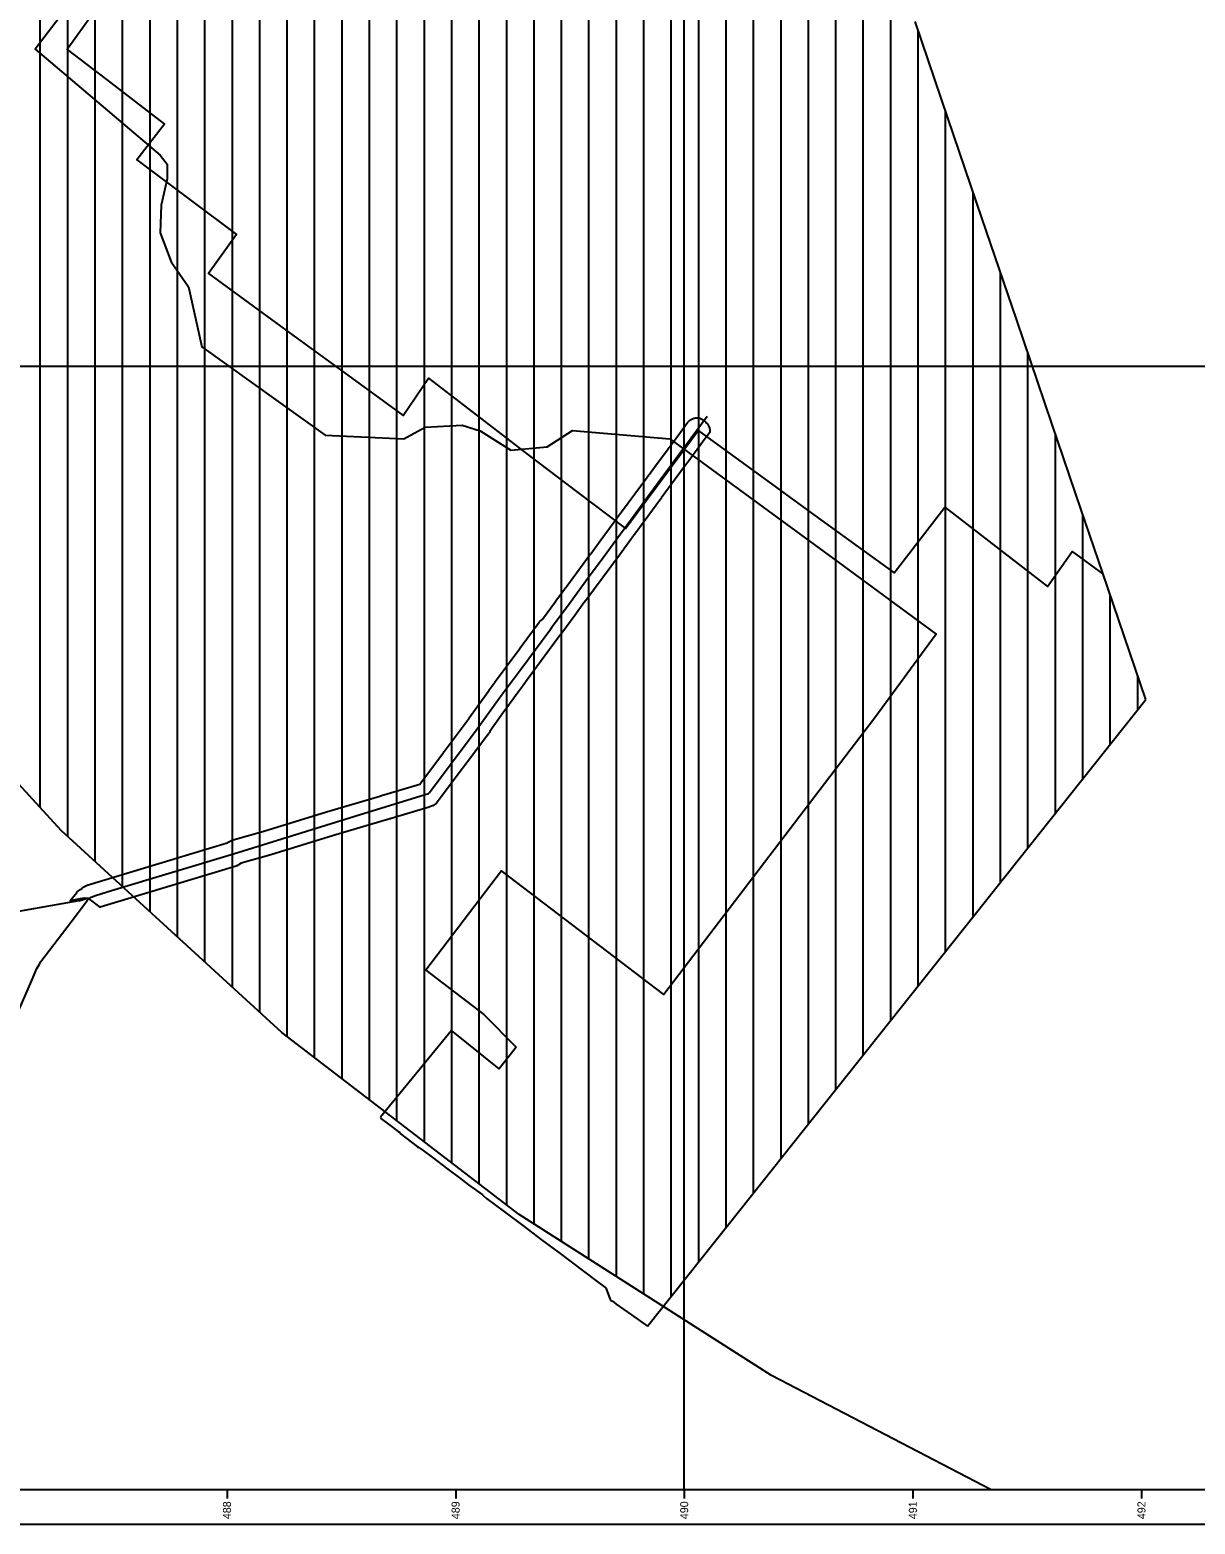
# Model space of a CAD drawing. Extents: x 468834 to 503362, y 294936 to 320859.
# Drawn here: x 487137 to 492234, y 294936 to 301471 of the extents above; entities that cross this region are included whole.
import ezdxf

# ---------------------------------------------------------------- set-up
doc = ezdxf.new("R2010")
doc.units = 0
for name, color, linetype in [('7311020103_no 10 līdz 25 kilometriem garas dabiskas ūdensteces vides un dabas resursu aizsardzības aizsargjoslas teritorija lauku apvidos', 7, 'Continuous'), ('7311080102_vides un dabas resursu aizsardzības aizsargjoslas teritorija ap purvu ar platību lielāku par 100 hektāriem', 7, 'Continuous'), ('7312070202_navigācijas tehniskā līdzekļa aviācijas gaisa kuģu lidojumu drošības nodrošināšanai tālās ietekmes zona', 7, 'Continuous'), ('aizkrāsojums-lidlauka tālās ietekmes zona', 7, 'Continuous'), ('Dabas lieguma robeža', 7, 'Continuous'), ('Koplietošanas novadgrāvis', 7, 'Continuous'), ('ramis', 7, 'Continuous'), ('Valsts nozīmes udensnotekas', 7, 'Continuous')]:
    doc.layers.add(name, color=color, linetype=linetype)

msp = doc.modelspace()

# ---------------------------------------------------------------- linework, layer by layer
at = {"layer": '7311020103_no 10 līdz 25 kilometriem garas dabiskas ūdensteces vides un dabas resursu aizsardzības aizsargjoslas teritorija lauku apvidos'}
msp.add_lwpolyline([(488039.3, 297814.4), (487444.5, 297634.8), (487402.8, 297666.2), (487400.7, 297667.6), (487400, 297668.1), (487393, 297672.5), (487379.5, 297673.6), (487375.7, 297673.9), (487356.8, 297670.6), (487313.3, 297662.3), (487316.9, 297666.8), (487342.1, 297698.8), (487344.9, 297702.1), (487349.5, 297706.4), (487354.6, 297710.1), (487360.1, 297713.1), (487364.7, 297715), (487366.4, 297717.1), (487371, 297721.4), (487376.1, 297725.1), (487381.6, 297728.1), (487387.4, 297730.4), (487388.4, 297730.7), (487763.9, 297844.1), (487766.4, 297844.7), (487767.7, 297845.2), (487768.7, 297845.5), (487999.9, 297915.4), (488002.2, 297916.9), (488007.7, 297919.9), (488010.6, 297921.1), (488013, 297922.9), (488018.6, 297925.9), (488024.4, 297928.2), (488026.1, 297928.7), (488160.9, 297967.2), (488434.2, 298050.9), (488668, 298120.5), (488671.5, 298121.3), (488673.5, 298122.1), (488675.3, 298122.7), (488843.4, 298172.7), (488946.3, 298310.4), (488946.7, 298310.8), (488948.2, 298312.7), (488948.4, 298313), (488950, 298315.3), (489050.4, 298448.8), (489054, 298453.6), (489054.8, 298454.7), (489055.4, 298456), (489056.9, 298458.9), (489058.7, 298461.6), (489059.5, 298462.9), (489115.3, 298541.1), (489146.1, 298584.2), (489146.5, 298584.9), (489172.5, 298620), (489173, 298620.8), (489174, 298622), (489174.7, 298623.1), (489279.8, 298765.5), (489280.7, 298766.5), (489280.8, 298766.8), (489282.2, 298768.7), (489364.8, 298880.8), (489365.4, 298881.5), (489367.5, 298884), (489369.7, 298886.4), (489372.1, 298888.7), (489374.6, 298890.7), (489377.3, 298892.7), (489379.6, 298894.1), (489379.8, 298894.3), (489436.8, 298972.1), (489436.9, 298972.3), (489477.1, 299026.6), (489477.7, 299027.3), (489479.7, 299029.9), (489481.9, 299032.1), (489482, 299032.5), (489485.5, 299038), (489590.3, 299179.5), (489590.5, 299179.9), (489632.1, 299236.1), (489693.5, 299319.8), (489697, 299324.7), (489698.2, 299326.1), (489698.2, 299326.1), (489699.5, 299328), (489725.5, 299363.2), (489812.7, 299481.7), (489813.3, 299482.4), (489813.8, 299483.1), (489815.1, 299484.9), (489845.2, 299525.8), (489847.3, 299528.5), (489847.4, 299528.6), (489876.9, 299568.5), (489930.8, 299641.3), (489931.3, 299641.9), (489932, 299642.7), (489933.2, 299644.5), (489959.8, 299680.3), (489959.8, 299680.4), (490014.5, 299754.4), (490015.1, 299755.1), (490017.2, 299757.7), (490019.4, 299760), (490021.8, 299762.3), (490024.3, 299764.4), (490027, 299766.3), (490029.7, 299768), (490032.6, 299769.5), (490035.6, 299770.9), (490038.7, 299772), (490041.8, 299773), (490045, 299773.7), (490048.2, 299774.3), (490051.5, 299774.6), (490054.7, 299774.7), (490058, 299774.6), (490061.3, 299774.3), (490064.5, 299773.7), (490067.7, 299773), (490070.8, 299772), (490073.9, 299770.9), (490076.9, 299769.5), (490079.7, 299768), (490082.5, 299766.3), (490085.2, 299764.4), (490087.7, 299762.3), (490090.1, 299760), (490092.3, 299757.7), (490094.4, 299755.1), (490094.6, 299754.9), (490094.6, 299754.8), (490097, 299752.6), (490099.3, 299750.2), (490101.3, 299747.7), (490103.3, 299745), (490105, 299742.2), (490106.5, 299739.4), (490107.9, 299736.4), (490109, 299733.3), (490110, 299730.2), (490110.7, 299727), (490111.3, 299723.8), (490111.6, 299720.5), (490111.7, 299717.2), (490111.6, 299714), (490111.3, 299710.7), (490082.9, 299672), (490072.2, 299657.4), (490040.2, 299614.2), (490040.2, 299614.1), (490016.8, 299582.5), (490016.3, 299581.9), (490015.7, 299581.1), (490014.4, 299579.3), (489930.9, 299466.8), (489898.9, 299423.2), (489898.3, 299422.4), (489897.3, 299421.2), (489896.6, 299420.1), (489783.2, 299266.2), (489781.6, 299264.3), (489780.9, 299263.2), (489777.3, 299258.3), (489715.9, 299174.4), (489569.5, 298976.5), (489561, 298965.1), (489520.6, 298910.5), (489463.6, 298832.8), (489463, 298831.9), (489460.9, 298829.4), (489458.7, 298827), (489456.7, 298825.2), (489455.3, 298822.2), (489451.8, 298816.7), (489312.7, 298628.2), (489294.7, 298603.8), (489277.1, 298580), (489261.1, 298558.2), (489242, 298532.3), (489233.7, 298521.1), (489227.9, 298512.9), (489209.7, 298487.5), (489149.5, 298403.1), (489148.7, 298401.3), (489147.2, 298398.4), (489145.4, 298395.7), (489143.8, 298393.4), (489140.3, 298388.6), (489034.2, 298247.5), (488919.5, 298094.2), (488915.8, 298089.8), (488915.4, 298089.4), (488910.8, 298085.1), (488910.2, 298084.6), (488905.1, 298080.9), (488899.6, 298077.9), (488899.1, 298077.6), (488894.2, 298075.6), (488886.9, 298073.1), (488886.3, 298072.8), (488885.6, 298072.6), (488885, 298072.4), (488884.4, 298072.2), (488717.2, 298022.5), (488715.2, 298022), (488714.2, 298021.6), (488712.4, 298021), (488702.8, 298018.2), (488701.5, 298017.8), (488700.1, 298017.5), (488699.2, 298017.1), (488698, 298016.7), (488465.5, 297947.5), (488191.8, 297863.7), (488191.2, 297863.5), (488061.2, 297826.4), (488054.8, 297822), (488053.8, 297821.2), (488053.1, 297820.8), (488052.8, 297820.6), (488051.5, 297819.8), (488050.9, 297819.4), (488049.2, 297818.5), (488048.1, 297818), (488048.1, 297817.9), (488046.7, 297817.2), (488043.7, 297815.9), (488043.1, 297815.7), (488040.3, 297814.7)], close=True, dxfattribs=at)
at = {"layer": '7311080102_vides un dabas resursu aizsardzības aizsargjoslas teritorija ap purvu ar platību lielāku par 100 hektāriem'}
for p, q in [((491154.7, 301082.1), (491009.9, 301508)), ((491301.7, 300649.8), (491154.7, 301082.1)), ((491454.2, 300201.4), (491301.7, 300649.8)), ((491607.9, 299749.3), (491454.2, 300201.4)), ((491736.2, 299372.2), (491607.9, 299749.3)), ((491830.1, 299095.8), (491736.2, 299372.2)), ((492018.5, 298543), (491830.1, 299095.8)), ((490242.8, 296309.4), (492018.5, 298543)), ((489264.7, 297022.9), (489250.2, 297002.6)), ((488671.4, 296716.6), (488672.6, 296710.3)), ((488672.6, 296710.3), (488706.1, 296685.9)), ((488706.1, 296685.9), (488748.8, 296653.3)), ((488748.8, 296653.3), (488755.6, 296649.4)), ((488755.6, 296649.4), (488755.1, 296648.2)), ((488755.1, 296648.2), (488757.2, 296645)), ((488757.2, 296645), (488831.6, 296587.7)), ((488831.6, 296587.7), (488838.9, 296583.7)), ((488838.9, 296583.7), (488857, 296569.9)), ((488857, 296569.9), (488897.4, 296540.7)), ((488897.4, 296540.7), (488965.6, 296488.8)), ((488965.6, 296488.8), (489016, 296450.2)), ((489016, 296450.2), (489056, 296420.6)), ((489056, 296420.6), (489115.1, 296377.4)), ((489115.1, 296377.4), (489121.1, 296372)), ((489121.1, 296372), (489135.1, 296360.4)), ((489135.1, 296360.4), (489214, 296301.6)), ((489839, 295801.5), (490242.8, 296309.4)), ((489214, 296301.6), (489299.3, 296237.8)), ((489299.3, 296237.8), (489374.6, 296179.7)), ((489374.6, 296179.7), (489451.5, 296123.5)), ((489451.5, 296123.5), (489613, 296001.4)), ((489613, 296001.4), (489652.9, 295972)), ((489652.9, 295972), (489656.7, 295969.4)), ((489656.7, 295969.4), (489675.1, 295919.3)), ((489675.1, 295919.3), (489677.8, 295916)), ((489677.8, 295916), (489685.9, 295911.2)), ((489685.9, 295911.2), (489691.4, 295907.3)), ((489691.4, 295907.3), (489702.4, 295898.3)), ((489702.4, 295898.3), (489769.6, 295851.2)), ((489769.6, 295851.2), (489839, 295801.5))]:
    msp.add_line(p, q, dxfattribs=at)
for points in [[(487526.7, 301866.5), (487160.6, 301386.5), (487707.9, 300924.2), (487738.1, 300884.3), (487738.5, 300819.9), (487712.2, 300704.5), (487707.6, 300583.1), (487755.5, 300457.6), (487831.5, 300348), (487889, 300084.8), (488429.4, 299698.7), (488773.4, 299682.9), (488865.8, 299733.8), (489027.7, 299743.1), (489107.4, 299717.6), (489240.6, 299633.3), (489400.1, 299647.2), (489510.6, 299719.5), (489647.1, 299707.9), (489936.1, 299683.1), (490671.6, 299144.5), (491102.3, 298829.1), (490833.5, 298462)], [(490833.5, 298462), (489909.8, 297252), (489200.5, 297793.4), (488869.3, 297359.4), (489123.1, 297165.8), (489264.7, 297022.9)], [(489250.2, 297002.6), (489190.6, 296927.8), (488981, 297094.7), (488671.4, 296716.6)]]:
    msp.add_lwpolyline(points, dxfattribs=at)
at = {"layer": '7312070202_navigācijas tehniskā līdzekļa aviācijas gaisa kuģu lidojumu drošības nodrošināšanai tālās ietekmes zona'}
msp.add_lwpolyline([(491342.5, 295086.2), (490381.1, 295586.7), (489277.5, 296289.8), (488239.3, 297086.4), (487274.5, 297970.5), (485919.8, 299448.9)], dxfattribs=at)
at = {"layer": 'aizkrāsojums-lidlauka tālās ietekmes zona'}
for p, q in [((487183, 298070.3), (487183, 314128.2)), ((487303, 297944.3), (487303, 314107.7)), ((487423, 297834.4), (487423, 314087.2)), ((487543, 297724.4), (487543, 314066.8)), ((487663, 297614.5), (487663, 314033.5)), ((487783, 297504.5), (487783, 313989.2)), ((487903, 297394.5), (487903, 313935)), ((488023, 297284.6), (488023, 313856.3)), ((488143, 297174.6), (488143, 313753.9)), ((488263, 297068.2), (488263, 313627.8)), ((488383, 296976.1), (488383, 312609)), ((488503, 296884.1), (488503, 312497.8)), ((489823, 295942.2), (489823, 312426.6)), ((489583, 296095.1), (489583, 312321.7)), ((489703, 296018.7), (489703, 312364.9)), ((488623, 296792), (488623, 312283.8)), ((488743, 296699.9), (488743, 312293.7)), ((489343, 296248), (489343, 312268)), ((489463, 296171.6), (489463, 312288.6)), ((489223, 296331.6), (489223, 312197.8)), ((489103, 296423.7), (489103, 312186.2)), ((488863, 296607.8), (488863, 312118.9)), ((488983, 296515.7), (488983, 312116.2)), ((489943, 295932.4), (489943, 304640.4)), ((490063, 296083.3), (490063, 304292.3)), ((490183, 296234.3), (490183, 303939.4)), ((490303, 296385.2), (490303, 303586.5)), ((490423, 296536.2), (490423, 303233.6)), ((490543, 296687.1), (490543, 302880.8)), ((490663, 296838), (490663, 302527.9)), ((490783, 296989), (490783, 302175)), ((490903, 297139.9), (490903, 301822.2)), ((491023, 297290.9), (491023, 301469.3)), ((491143, 297441.8), (491143, 301116.4)), ((491263, 297592.7), (491263, 300763.5)), ((491383, 297743.7), (491383, 300410.6)), ((491503, 297894.6), (491503, 300057.7)), ((491623, 298045.5), (491623, 299704.9)), ((491743, 298196.5), (491743, 299352)), ((491863, 298347.4), (491863, 298999.3)), ((491983, 298498.4), (491983, 298647.2))]:
    msp.add_line(p, q, dxfattribs=at)
at = {"layer": 'Dabas lieguma robeža'}
for p, q in [((491154.7, 301082.1), (491009.9, 301508)), ((491301.7, 300649.8), (491154.7, 301082.1)), ((491454.2, 300201.4), (491301.7, 300649.8)), ((491607.9, 299749.3), (491454.2, 300201.4)), ((491736.2, 299372.2), (491607.9, 299749.3)), ((491830.1, 299095.8), (491736.2, 299372.2)), ((491831.8, 299090.9), (491830.1, 299095.8))]:
    msp.add_line(p, q, dxfattribs=at)
msp.add_lwpolyline([(487415.1, 301545.9), (487301.2, 301385.7), (487472.9, 301253.8), (487726.2, 301059.2), (487605.8, 300903.6), (487837.9, 300728.8), (488041, 300575.8), (487918.8, 300405.4), (488271.4, 300148.6), (488495.9, 299985.1), (488769.9, 299785.5), (488881, 299948.4), (489032.3, 299831.8), (489316.9, 299612.2), (489533.5, 299448.7), (489742.3, 299291.2), (489792.3, 299358.3), (489919, 299528.5), (490060.9, 299719), (490242.3, 299587.2), (490365, 299498.1), (490571.2, 299348.2), (490786.7, 299191.4), (490917.5, 299096.4), (491139.9, 299383.5), (491588.2, 299037.5), (491696.5, 299190), (491831.8, 299090.9)], dxfattribs=at)
at = {"layer": 'Koplietošanas novadgrāvis'}
for points in [[(487351.1, 297662.7), (486863.2, 297576.9), (486687.4, 297543.3)], [(487351.1, 297662.7), (487393.9, 297676)]]:
    msp.add_lwpolyline(points, dxfattribs=at)
at = {"layer": 'ramis'}
for p, q in [((500923.3, 295086.2), (468983.8, 295086.2)), ((488000, 295086.2), (488000, 295048.1)), ((489000, 295086.2), (489000, 295048.1)), ((490000, 295086.2), (490000, 295048.1)), ((491000, 295086.2), (491000, 295048.1)), ((492000, 295086.2), (492000, 295048.1))]:
    msp.add_line(p, q, dxfattribs=at)
msp.add_lwpolyline([(501073.3, 316810.3), (468833.8, 316810.3), (468833.8, 294936.2), (501073.3, 294936.2)], close=True, dxfattribs=at)
for points in [[(490000, 295086.2), (490000, 316660.3)], [(482061.2, 300000), (500923.3, 300000)]]:
    msp.add_lwpolyline(points, dxfattribs=at)
at = {"layer": 'Valsts nozīmes udensnotekas'}
msp.add_lwpolyline([(487079.9, 297164), (487143.9, 297310.5), (487168.4, 297366.2), (487179, 297385.7), (487185.5, 297396.7), (487318.5, 297570.9), (487368.3, 297636.2), (487388.4, 297663), (487400.5, 297675.3), (487405.9, 297678.6), (487424.2, 297685.9), (487494.3, 297707.7), (488027.8, 297867.9), (488600.6, 298045), (488880.3, 298131.5), (488885, 298135.5), (489089.7, 298409.3), (489202.7, 298565.5), (489285.9, 298676.8), (489411.3, 298846.5), (489423.7, 298863.6), (489500, 298966.5), (489581.3, 299078.1), (489645.5, 299164.4), (489840.9, 299430), (490100.3, 299782.4)], dxfattribs=at)

# ---------------------------------------------------------------- texts
at = {"layer": 'ramis'}
for s, p in [('488', (488017, 294957.8)), ('489', (489017, 294957.8)), ('490', (490017, 294957.8)), ('491', (491017, 294957.8)), ('492', (492017, 294957.8))]:
    msp.add_text(s, height=35, rotation=90, dxfattribs=at).set_placement(p)

doc.saveas('drawing.dxf')
